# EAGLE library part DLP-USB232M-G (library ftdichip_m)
DLP-USB232M-G USB - SERIAL UART Interface Module Source: http://www.ftdichip.com/Documents/DataSheets/DLP/dlp-usb232m15.pdf
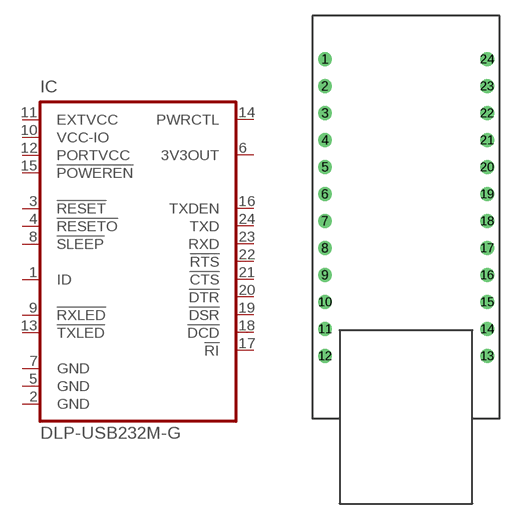
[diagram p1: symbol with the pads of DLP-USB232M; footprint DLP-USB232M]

Designator prefix IC

## DLP-USB232M-G (OC_FARNELL: unknown; OC_NEWARK: unknown)  [DLP-USB232M]
1  ID  in
2  GND  in
3  !RESET  in
4  !RESETO  in
5  GND  in
6  3V3OUT  in
7  GND  in
8  !SLEEP  in
9  !RXLED  in
10  VCC-IO  in
11  EXTVCC  in
12  PORTVCC  in
13  !TXLED  in
14  PWRCTL  in
15  !POWEREN  in
16  TXDEN  in
17  !RI  in
18  !DCD  in
19  !DSR  in
20  !DTR  in
21  !CTS  in
22  !RTS  in
23  RXD  in
24  TXD  in

## Footprint DLP-USB232M (pad centres in mm)
DLP-USB232M-G USB - SERIAL UART Interface Module Source: http://www.ftdichip.com/Documents/DataSheets/DLP/dlp-usb232m15.pdf
drill 0.8 pad 1.27 round: 1 -7.62,27.94; 2 -7.62,25.4; 3 -7.62,22.86; 4 -7.62,20.32; 5 -7.62,17.78; 6 -7.62,15.24; 7 -7.62,12.7; 8 -7.62,10.16; 9 -7.62,7.62; 10 -7.62,5.08; 11 -7.62,2.54; 12 -7.62,0; 13 7.62,0; 14 7.62,2.54; 15 7.62,5.08; 16 7.62,7.62; 17 7.62,10.16; 18 7.62,12.7; 19 7.62,15.24; 20 7.62,17.78; 21 7.62,20.32; 22 7.62,22.86; 23 7.62,25.4; 24 7.62,27.94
